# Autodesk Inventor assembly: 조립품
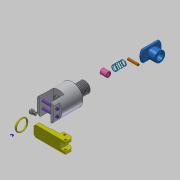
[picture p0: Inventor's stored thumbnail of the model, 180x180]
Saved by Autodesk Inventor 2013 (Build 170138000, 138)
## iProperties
Created: 2019-02
Part Number: 조립품
Document SubType Name: Assembly
Designer: dgall
Author: dgall
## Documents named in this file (11)
- C:\Users\dgall\Desktop\490207V1007\조립품.iam
- C:\Users\dgall\Desktop\490207V1007\본체.ipt
- C:\Users\dgall\Desktop\490207V1007\E-링.ipt
- C:\Users\dgall\Desktop\490207V1007\O-링.ipt
- C:\Users\dgall\Desktop\490207V1007\가이드핀.ipt
- C:\Users\dgall\Desktop\490207V1007\부시.ipt
- C:\Users\dgall\Desktop\490207V1007\스프링.ipt
- C:\Users\dgall\Desktop\490207V1007\평행핀 6x28.ipt
- C:\Users\dgall\Desktop\490207V1007\피스톤.ipt
- C:\Users\dgall\Desktop\490207V1007\핀.ipt
- C:\Users\dgall\Desktop\490207V1007\핑거.ipt
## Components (7 placed, 6 different names)
1. E-링:1
2. O-링:1
3. 가이드핀:1
4. 피스톤:1
5. 핀:1 — 플러쉬:2
6. 핀:2 — 플러쉬:1
7. 핑거:1
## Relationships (2: Flush 2)
- 플러쉬:1 [Flush]: 핀:2
- 플러쉬:2 [Flush]: 핀:1
